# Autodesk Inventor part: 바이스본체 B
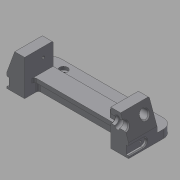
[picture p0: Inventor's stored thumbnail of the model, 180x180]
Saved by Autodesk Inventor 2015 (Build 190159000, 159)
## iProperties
Created: 2017-04
Part Number: 바이스본체 B
Material: 일반
Document SubType Name: Modeling
Designer: mduedu
Density: 1 g/cm^3
Appearance: 기본값
Mass: 119.615 g
Surface Area: 275.767 cm^2
Volume: 119.615 cm^3
Author: mduedu
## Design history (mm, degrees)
sketch "스케치1"
  geometry: L1 (-75, 0)-(75, 0); L2 (-75, 0)-(-75, 17); L3 (-53, 17)-(53, 17); L4 (75, 17)-(75, 0); L5 (-75, 17)-(-65.173, 44); L6 (-65.173, 44)-(-53, 44); L7 (-53, 44)-(-53, 17); L8 (0, 0)-(0, 17); L9 (75, 17)-(65.173, 44); L10 (65.173, 44)-(53, 44); L11 (53, 44)-(53, 17); 1 further point
  constraints: 22 end point, 4 perpendicular, 2 horizontal alignment, 2 midpoint, 2 symmetric about line, 1 coincident, 1 collinear, 1 horizontal, 1 vertical
  dimensions: "d0" = 150 distance of L1.start L1.end; "d1" = 17 distance of L1.start L2.end; "d2" = 27 distance of L3.start L6.end; "d3" = 22 distance of L3.start L2.end; "d4" = 70 deg angle of L3 L5; "d54" = 20 deg angle of L9 L4
extrude "돌출1" new body sketch "스케치1" stored distance "d5" = 70; taper "d6" = 0 deg
sketch "스케치2"
  geometry: L1 (0, 70)-(106, 70) reference; L2 (106, 70)-(106, 0) reference; L3 (106, 0)-(0, 0) reference; L4 (0, 47)-(106, 47); L5 (106, 47)-(106, 23); L6 (106, 23)-(0, 23); L7 (0, 23)-(0, 47); L8 (0, 70)-(0, 0) reference; 2 further points
  constraints: 8 end point, 2 parallel, 2 point on line, 1 horizontal, 1 horizontal alignment, 1 midpoint, 1 perpendicular
  dimensions: "d7" = 24 distance between parallel lines of L6 L4
extrude "돌출2" cut sketch "스케치2" stored distance "d9" = 70; taper "d10" = 0 deg
sketch "스케치3"
  geometry: L1 (22, -23)-(128, -23) reference; L2 (128, -47)-(22, -47) reference; L3 (22, -18)-(128, -18); L4 (128, -52)-(22, -52); L5 (22, -18)-(22, -52); L6 (128, -18)-(128, -52); 1 further point
  constraints: 8 end point, 3 parallel, 2 point on line, 1 perpendicular
  dimensions: "d11" = 5 distance between parallel lines of L3 L1; "d12" = 5 distance between parallel lines of L4 L2
extrude "돌출3" cut sketch "스케치3" distance "d13" = 12; taper "d14" = 0 deg
fillet "모깎기1" dims "d15" = 3, "d16" = 3
sketch "스케치4"
  geometry: L1 (103, 23)-(3, 23) reference; L2 (0, 26)-(0, 0) reference; L3 (106, 0)-(0, 0) reference; L4 (106, 26)-(106, 0) reference; L5 (96, 0)-(90, 0); L6 (90, 0)-(90, 19.5); L7 (96, 19.5)-(96, 0); L8 (90, 19.5)-(96, 19.5); A1 r 3 centre (3, 26) between (0, 26) and (3, 23) reference; A2 r 3 centre (103, 26) between (103, 23) and (106, 26) reference; 1 further point
  constraints: 8 end point, 2 perpendicular, 1 horizontal, 1 parallel, 1 point on line
  dimensions: "d17" = 10 distance between parallel lines of L7 L4; "d18" = 6 distance between parallel lines of L7 L6; "d27" = 3.5 distance between parallel lines of L8 L1
extrude "돌출4" join sketch "스케치4" distance "d19" = 12; taper "d20" = 0 deg
chamfer "모따기1" distance "d21" = 3; stored, may be unused: second distance "d22" = 2, angle "d23" = 45 deg
chamfer "모따기2" distance "d24" = 3; stored, may be unused: second distance "d25" = 2, angle "d26" = 45 deg
sketch "스케치5"
  geometry: L1 (-15.5, 35.8)-(-15.5, -25.8) reference; L2 (19.5, 0)-(0, 0) reference; C1 r 6.5 at (9.5, 15); 1 further point
  constraints: 1 centre point
  dimensions: "d28" = 13 diameter of C1; "d30" = 15 distance from line of C1.centre L2; "d31" = 25 distance from line of C1.centre L1
extrude "돌출5" cut sketch "스케치5" stored distance "d32" = 12; taper "d33" = 0 deg
sketch "스케치6"
  geometry: C1 r 5 at (-10, 15); C2 r 5 at (-60, 15); A1 r 6.5 centre (-10, 15) between (-15.766, 12) and (-4.234, 12) reference; A2 r 6.5 centre (-60, 15) between (-65.766, 12) and (-54.234, 12) reference; 1 further point
  constraints: 2 centre point, 2 coincident
  dimensions: "d34" = 10 diameter of C1; "d35" = 10 diameter of C2 (= d34)
extrude "돌출6" cut sketch "스케치6" stored distance "d36" = 12; taper "d37" = 0 deg
chamfer "모따기3" distance "d38" = 1; stored, may be unused: second distance "d39" = 2, angle "d40" = 45 deg
chamfer "모따기4" distance "d41" = 1; stored, may be unused: second distance "d42" = 2, angle "d43" = 45 deg
sketch "스케치7"
  geometry: L1 (-35, 35.8)-(-35, -25.8) reference; L2 (-70, 0)-(0, 0) reference; C1 r 5 at (-35, 15); 1 further point
  constraints: 1 centre point, 1 point on line
  dimensions: "d44" = 10 diameter of C1; "d45" = 15 distance from line of C1.centre L2
extrude "돌출7" cut sketch "스케치7" stored distance "d46" = 12; taper "d47" = 0 deg
chamfer "모따기5" distance "d48" = 1; stored, may be unused: second distance "d49" = 2, angle "d50" = 45 deg
node "작업축1"
sketch "스케치8"
  geometry: L1 (-105, 32)-(105, 32) reference; L2 (58, 32)-(64, 32); L3 (64, 32)-(64, 40); L4 (64, 40)-(58, 40); L5 (58, 40)-(58, 32); L6 (53, 38)-(53, 26) reference; 1 further point
  constraints: 8 end point, 2 parallel, 1 horizontal, 1 perpendicular, 1 point on line
  dimensions: "d51" = 5 distance from line of L6 L2.start; "d52" = 6 distance of L3.end L4.end; "d53" = 16 diameter of L4 L1
revolve "회전1" sketch "스케치8" stored, may be unused: angle "d55" = 90 deg
fillet "모깎기2"
chamfer "모따기6" distance "d56" = 1; stored, may be unused: second distance "d57" = 2, angle "d58" = 45 deg
sketch "스케치9"
  geometry: L1 (17.5, 3)-(52.5, 3); L2 (52.5, 13)-(17.5, 13); L3 (70, 0)-(0, 0) reference; L4 (17.5, 8)-(52.5, 8); A1 r 5 centre (17.5, 8) between (17.5, 13) and (17.5, 3); A2 r 5 centre (52.5, 8) between (52.5, 3) and (52.5, 13); 3 further points
  constraints: 6 end point, 4 point on circle, 3 tangent, 2 centre point, 2 midpoint, 2 parallel, 1 horizontal, 1 vertical alignment
  dimensions: "d59" = 35 distance of L4.start L4.end; "d61" = 5 radius of A2; "d62" = 8 distance between parallel lines of L3 L4
extrude "돌출8" cut sketch "스케치9" distance "d63" = 3; taper "d64" = 0 deg
chamfer "모따기7" distance "d65" = 1; stored, may be unused: second distance "d66" = 2, angle "d67" = 45 deg
chamfer "모따기8" distance "d68" = 1; stored, may be unused: second distance "d69" = 2, angle "d70" = 45 deg
feature "분할1"
sketch "스케치10"
  geometry: A1 r 5 centre (0, 0) between (0, 5) and (0, -5) reference; 1 further point
  constraints: 1 coincident
hole "구멍1" sketch "스케치10" at (0, 0) diameter "d71" = 2.459; stored, may be unused: countersink angle "d75" = 90 deg, drill point angle "d77" = 120 deg; dims "d72" = 4.5, "d73" = 4, "d74" = 2, "d76" = 6
sketch "스케치11"
  geometry: L1 (0, 0)-(0, 27) reference; L2 (0, 27)-(-35, 27) reference; 2 further points
  dimensions: "d78" = 12 distance from line of point (-12, 15.5) L1; "d79" = 11.5 distance from line of point (-12, 15.5) L2
hole "구멍2" sketch "스케치11" at (-12, 15.5) diameter "d80" = 3.242; stored, may be unused: countersink angle "d84" = 90 deg, drill point angle "d86" = 120 deg; dims "d81" = 6, "d82" = 4, "d83" = 2, "d85" = 8
sketch "스케치12"
  geometry: L1 (-75, -35)-(-75, 0) reference; L2 (75, -35)-(75, 0) reference; L3 (75, -35)-(-75, -35); L4 (-75, -35)-(-75, -55); L5 (-75, -55)-(75, -55); L6 (75, -55)-(75, -35); 1 further point
  constraints: 8 end point, 2 parallel, 1 horizontal, 1 perpendicular, 1 point on line
  dimensions: "d87" = 20 distance of L3.end L4.end; "d89" = 150 distance of L4.end L5.end (derived)
extrude "돌출9" join sketch "스케치12" distance "d90" = 10; taper "d91" = 0 deg
sketch "스케치13"
  geometry: L1 (-75, 55)-(-75, 35) reference; L2 (75, 35)-(75, 55) reference; L3 (-75, 45)-(75, 45); 3 further points
  constraints: 2 end point, 2 midpoint, 2 point on line
  dimensions: "d92" = 50 horizontal distance of point (-50, 45) point (0, 0); "d93" = 100 distance of point (50, 45) point (-50, 45)
fillet "모깎기3" dims "d94" = 12
chamfer "모따기9" distance "d95" = 1; stored, may be unused: second distance "d96" = 2, angle "d97" = 45 deg
hole "구멍3" sketch "스케치13" diameter "d98" = 4.134; stored, may be unused: countersink angle "d102" = 90 deg, drill point angle "d104" = 118 deg; dims "d99" = 6, "d100" = 10, "d101" = 4, "d103" = 8
node "솔리드1"
mirror "대칭1"
mirror "대칭2"
mirror "대칭3"
mirror "대칭4"
node "투영된 루프1"
